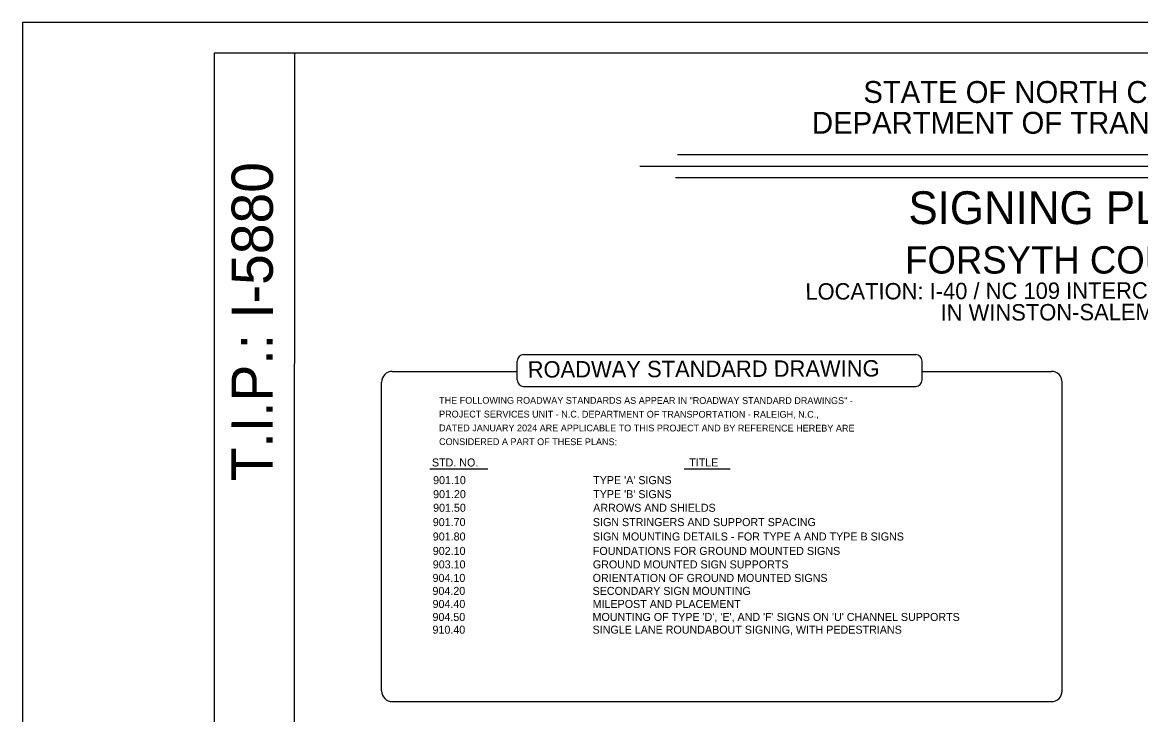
# Model space of a CAD drawing. Extents: x 49201 to 52602, y 49383 to 50479.
# Drawn here: x 50703 to 51649, y 49894 to 50479 of the extents above; entities that cross this region are included whole.
import ezdxf

# ---------------------------------------------------------------- set-up
doc = ezdxf.new("R2010")
doc.units = 0
for name, color, linetype in [('Default', 7, 'Continuous'), ('DEV TITLE SHEET CELL', 7, 'Continuous'), ('Old_Level_18', 7, 'Continuous'), ('Sheet Plot Border Outside CELL', 7, 'Continuous'), ('Sheet Title CELL', 7, 'Continuous')]:
    doc.layers.add(name, color=color, linetype=linetype)

msp = doc.modelspace()

# ---------------------------------------------------------------- linework, layer by layer
at = {"layer": 'Default'}
for points in [[(51257.44, 50367.56), (51951.23, 50367.56)], [(51225.48, 50357.8), (51979.89, 50357.8)], [(51255.76, 50348.05), (51949.56, 50348.05)]]:
    msp.add_lwpolyline(points, dxfattribs=at)
at = {"layer": 'Old_Level_18'}
msp.add_lwpolyline([(52365.34, 50453.17), (50865.34, 50453.17), (50865.34, 49403.17), (52365.34, 49403.17)], close=True, dxfattribs=at)
at = {"layer": 'Sheet Plot Border Outside CELL'}
msp.add_lwpolyline([(52386.04, 50479.27), (50703.13, 50479.27), (50703.13, 49383.36), (52386.04, 49383.36)], close=True, dxfattribs=at)
at = {"layer": 'Sheet Title CELL'}
for p, q in [((51121.74, 50176.87), (51121.74, 50192.9)), ((51464.29, 50176.87), (51464.29, 50192.9)), ((51016.07, 50184.09), (51121.74, 50184.09)), ((51464.29, 50184.09), (51573.67, 50184.09)), ((51006.99, 49913.92), (51006.99, 50175)), ((51582.76, 49913.92), (51582.76, 50175)), ((51047.78, 50101.75), (51097.02, 50101.75)), ((51263, 50101.75), (51301.83, 50101.75)), ((51016.07, 49904.83), (51573.67, 49904.83))]:
    msp.add_line(p, q, dxfattribs=at)
for points in [[(50933.09, 49403.17), (50933.65, 50453.17)], [(51127.2, 50198.35), (51458.84, 50198.35)], [(51127.2, 50171.42), (51458.84, 50171.42)]]:
    msp.add_lwpolyline(points, dxfattribs=at)
for centre, radius, start, end in [((51127.2, 50192.9), 5.45, 90, 180), ((51458.84, 50192.9), 5.45, 0, 90), ((51016.07, 50175), 9.09, 90, 180), ((51127.2, 50176.87), 5.45, 180, 270), ((51458.84, 50176.87), 5.45, 270, 0), ((51573.67, 50175), 9.09, 0, 90), ((51016.07, 49913.92), 9.09, 180, 270), ((51573.67, 49913.92), 9.09, 270, 0)]:
    msp.add_arc(centre, radius, start, end, dxfattribs=at)

# ---------------------------------------------------------------- texts
at = {"layer": 'Default'}
for s, height, rotation, p in [('STATE OF NORTH CAROLINA', 18.4936, 360, (51414.58, 50411.15)), ('DEPARTMENT OF TRANSPORTATION', 18.4936, 360, (51371.15, 50385.12)), ('T.I.P.: I-5880', 34.925, 89.96919, (50914.95, 50091.18)), ('SIGNING PLAN', 27.7403, 360, (51452.71, 50308.68)), ('FORSYTH COUNTY', 23.1165, 360, (51449.94, 50266.86)), ('LOCATION: I-40 / NC 109 INTERCHANGE PROJECT', 13.8702, 0.18224, (51365.54, 50244.76)), ('IN WINSTON-SALEM, NC', 13.8702, 0.18224, (51479.94, 50226.94)), ('ROADWAY STANDARD DRAWING', 13.8661, 0.18224, (51130.65, 50178.86))]:
    msp.add_text(s, height=height, rotation=rotation, dxfattribs=at).set_placement(p)
for s, height, p in [('STD. NO.', 6.771, (51049.61, 50103.71)), ('TITLE', 6.771, (51267.27, 50103.71)), ('901.10', 6.771, (51050.6, 50088.78)), ("TYPE 'A' SIGNS", 6.7709, (51186.02, 50088.78)), ('901.20', 6.771, (51050.6, 50076.93)), ("TYPE 'B' SIGNS", 6.7709, (51186.02, 50076.93)), ('901.50', 6.771, (51050.6, 50065.41)), ('ARROWS AND SHIELDS', 6.7709, (51186.02, 50065.41)), ('901.70', 6.771, (51050.33, 50053.29)), ('SIGN STRINGERS AND SUPPORT SPACING', 6.7709, (51185.75, 50053.29)), ('901.80', 6.771, (51050.33, 50041.12)), ('SIGN MOUNTING DETAILS - FOR TYPE A AND TYPE B SIGNS', 6.7709, (51185.75, 50041.12)), ('902.10', 6.771, (51050.33, 50028.91)), ('FOUNDATIONS FOR GROUND MOUNTED SIGNS', 6.7709, (51185.75, 50028.91)), ('903.10', 6.771, (51050.33, 50017.52)), ('GROUND MOUNTED SIGN SUPPORTS', 6.7709, (51185.75, 50017.52)), ('904.10', 6.771, (51050.15, 50006.09)), ('ORIENTATION OF GROUND MOUNTED SIGNS', 6.7709, (51185.56, 50006.09)), ('904.20', 6.771, (51050.09, 49995.1)), ('SECONDARY SIGN MOUNTING', 6.7709, (51185.5, 49995.1)), ('904.40', 6.771, (51050.15, 49984.07)), ('MILEPOST AND PLACEMENT', 6.7709, (51185.56, 49984.07)), ('904.50', 6.771, (51050.09, 49973.08)), ("MOUNTING OF TYPE 'D', 'E', AND 'F' SIGNS ON 'U' CHANNEL SUPPORTS", 6.7709, (51185.5, 49973.08)), ('910.40', 6.771, (51050.09, 49962.32)), ('SINGLE LANE ROUNDABOUT SIGNING, WITH PEDESTRIANS', 6.7709, (51185.5, 49962.32))]:
    msp.add_text(s, height=height, dxfattribs=at).set_placement(p)
at = {"layer": 'DEV TITLE SHEET CELL'}
for s, p in [('THE FOLLOWING ROADWAY STANDARDS AS APPEAR IN "ROADWAY STANDARD DRAWINGS" -', (51055.66, 50156.8)), ('PROJECT SERVICES UNIT - N.C. DEPARTMENT OF TRANSPORTATION - RALEIGH, N.C.,', (51055.66, 50145.15)), ('DATED JANUARY 2024 ARE APPLICABLE TO THIS PROJECT AND BY REFERENCE HEREBY ARE ', (51055.65, 50133.49)), ('CONSIDERED A PART OF THESE PLANS:', (51055.64, 50121.84))]:
    msp.add_text(s, height=5.7256, rotation=359.9598, dxfattribs=at).set_placement(p)

doc.saveas('drawing.dxf')
